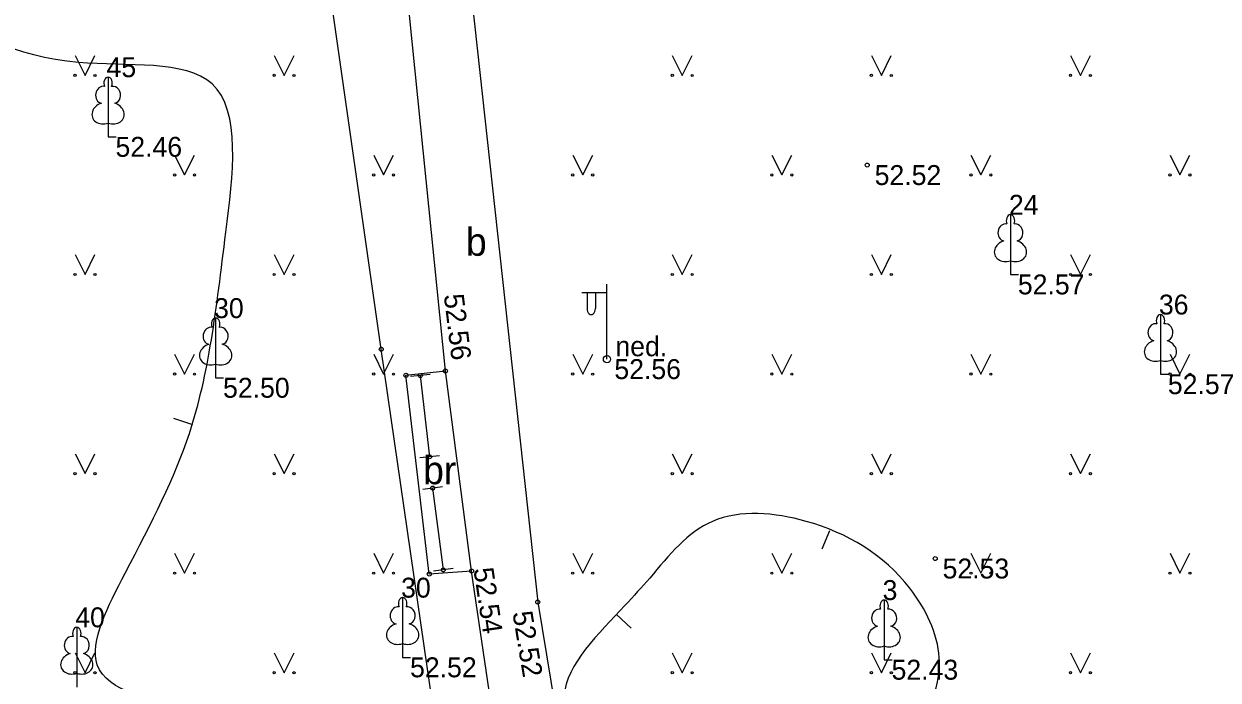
# Model space of a CAD drawing. Extents: x 619806 to 620082, y 405176 to 405386.
# Drawn here: x 619968.46 to 619998.46, y 405224.81 to 405241.29 of the extents above; entities that cross this region are included whole.
import ezdxf

# ---------------------------------------------------------------- set-up
doc = ezdxf.new("R2010")
doc.units = 0
for name, color, linetype in [('APGS_ELEM_####_####_#', 7, 'Continuous'), ('APGS_ELEM_####_TKST_#', 7, 'Continuous'), ('APGS_VADP_ZSPR_####_#', 7, 'Continuous'), ('BUVE_SOLS_####_####_#', 7, 'Continuous'), ('CELI_CMAL_####_####_#', 7, 'Continuous'), ('CELI_CSEG_####_TKST_#', 7, 'Continuous'), ('CELI_SEGL_####_####_#', 7, 'Continuous'), ('RELJ_AATZ_####_TKST_#', 7, 'Continuous'), ('RELJ_ELEM_####_####_#', 7, 'Continuous'), ('RELJ_HORZ_PAMT_####_#', 7, 'Continuous'), ('TERT_DIAM_####_TKST_#', 7, 'Continuous'), ('TERT_ELEM_####_####_#', 7, 'Continuous')]:
    doc.layers.add(name, color=color, linetype=linetype)

msp = doc.modelspace()

# ---------------------------------------------------------------- linework, layer by layer
at = {"layer": 'APGS_ELEM_####_####_#'}
for p, q in [((619983.109, 405234.542), (619982.474, 405234.537)), ((619982.609, 405234.538), (619982.609, 405234.146)), ((619982.819, 405234.54), (619982.819, 405234.146)), ((619983.109, 405232.875), (619983.109, 405234.758))]:
    msp.add_line(p, q, dxfattribs=at)
msp.add_circle((619983.109, 405232.875), 0.09, dxfattribs=at)
msp.add_ellipse((619982.714, 405234.146), major_axis=(0, 0.151), ratio=0.695971, start_param=1.570796, end_param=4.712389, dxfattribs=at)
at = {"layer": 'APGS_VADP_ZSPR_####_#'}
msp.add_lwpolyline([(619938.618, 405223.547), (619972.929, 405204.127), (619985.155, 405202.826), (619985.811, 405203.238), (619985.154, 405203.005), (619983.308, 405203.577), (619978.291, 405211.172), (619979.175, 405220.104), (619979.035, 405222.014), (619979.51, 405222.264), (619979.008, 405222.268), (619977.44, 405233.124), (619976.223, 405241.622), (619977.344, 405241.94), (619976.176, 405241.874), (619974.789, 405253.607), (619974.705, 405261.349), (619975.127, 405262.48)], dxfattribs=at)
at = {"layer": 'BUVE_SOLS_####_####_#'}
for p, q in [((619978.668, 405232.492), (619978.172, 405232.436)), ((619978.902, 405230.45), (619978.406, 405230.394)), ((619978.979, 405229.669), (619978.483, 405229.605)), ((619978.731, 405229.637), (619978.997, 405227.583)), ((619979.245, 405227.615), (619978.749, 405227.551))]:
    msp.add_line(p, q, dxfattribs=at)
msp.add_lwpolyline([(619978.42, 405232.464), (619978.654, 405230.422)], dxfattribs=at)
at = {"layer": 'CELI_CMAL_####_####_#'}
for points in [[(619982.283, 405204.018), (619982.381, 405205.526), (619981.404, 405213.543), (619980.879, 405217.395), (619980.193, 405224.262), (619979.707, 405227.554), (619978.646, 405227.479), (619978.06, 405232.469), (619979.052, 405232.579), (619978.008, 405242.924), (619976.591, 405255.672), (619975.781, 405263.512), (619969.844, 405259.482), (619963.066, 405254.752), (619955.624, 405249.587), (619947.422, 405243.791), (619942.081, 405239.98), (619941.835, 405240.299), (619936.133, 405229.455), (619943.441, 405225.387), (619954.092, 405219.528), (619965.106, 405213.442), (619974.994, 405207.99), (619982.283, 405204.018)], [(619978.832, 405249.941), (619981.369, 405226.774), (619981.804, 405224.124), (619982.441, 405217.773), (619982.996, 405213.675), (619983.965, 405205.418), (619983.685, 405203.225), (619985.778, 405202.103), (619986.248, 405201.889), (619987.106, 405201.651), (619987.96, 405201.56), (619988.713, 405201.545), (619992.1, 405202.316), (619994.967, 405203.071), (620002.119, 405213.03), (620010.184, 405224.469), (620017.253, 405234.372), (620024.304, 405244.304)]]:
    msp.add_lwpolyline(points, dxfattribs=at)
at = {"layer": 'CELI_SEGL_####_####_#'}
msp.add_lwpolyline([(619979.707, 405227.554), (619979.052, 405232.579)], dxfattribs=at)
at = {"layer": 'RELJ_ELEM_####_####_#'}
for centre in [(619989.646, 405237.748), (619977.44, 405233.124), (619978.06, 405232.469), (619978.42, 405232.464), (619979.052, 405232.579), (619978.654, 405230.422), (619978.731, 405229.637), (619991.352, 405227.867), (619978.997, 405227.583), (619979.707, 405227.554), (619978.646, 405227.479), (619981.369, 405226.774)]:
    msp.add_circle(centre, 0.05, dxfattribs=at)
at = {"layer": 'RELJ_HORZ_PAMT_####_#'}
for p, q in [((619972.222, 405231.391), (619972.697, 405231.236)), ((619988.513, 405228.108), (619988.709, 405228.568)), ((619983.72, 405226.123), (619983.351, 405226.459))]:
    msp.add_line(p, q, dxfattribs=at)
for points in [[(619952.192, 405242.46), (619958.269, 405245.178), (619960.212, 405247.147), (619962.71, 405245.388), (619969.834, 405240.326), (619973.191, 405239.787), (619973.537, 405236.062), (619972.621, 405231.011), (619971.007, 405227.497), (619970.308, 405225.195), (619972.877, 405224.18), (619975.834, 405223.443), (619975.125, 405220.25), (619977.669, 405218.792), (619978.775, 405216.928), (619978.459, 405213.841), (619976.501, 405213.003), (619972.992, 405212.359), (619969.535, 405213.328), (619966.616, 405215.931), (619967.251, 405218.057), (619966.078, 405220.067), (619963.269, 405223.678), (619959.906, 405226.02), (619956.916, 405226.372), (619951.315, 405227.272), (619948.301, 405227.78), (619946.134, 405229.326), (619943.292, 405232.49), (619942.821, 405234.331), (619944.296, 405235.783), (619946.209, 405238.021), (619948.046, 405239.888), (619950.691, 405241.967), (619952.192, 405242.46)], [(619984.185, 405227.378), (619985.762, 405228.802), (619988.112, 405228.802), (619990.713, 405227.124), (619991.454, 405225.372), (619990.633, 405223.024), (619987.075, 405219.79), (619984.539, 405219.79), (619983.041, 405222.072), (619982.032, 405224.412), (619983.558, 405226.687), (619984.185, 405227.378)]]:
    msp.add_spline(points, degree=3, dxfattribs=at)
at = {"layer": 'TERT_ELEM_####_####_#'}
for p, q in [((619969.75, 405240.5), (619970, 405240)), ((619970, 405240), (619970.25, 405240.5)), ((619974.75, 405240.5), (619975, 405240)), ((619975, 405240), (619975.25, 405240.5)), ((619984.75, 405240.5), (619985, 405240)), ((619985, 405240), (619985.25, 405240.5)), ((619989.75, 405240.5), (619990, 405240)), ((619990, 405240), (619990.25, 405240.5)), ((619994.75, 405240.5), (619995, 405240)), ((619995, 405240), (619995.25, 405240.5)), ((619970.58, 405238.804), (619970.58, 405238.457)), ((619970.58, 405238.457), (619970.78, 405238.457)), ((619972.25, 405238), (619972.5, 405237.5)), ((619972.5, 405237.5), (619972.75, 405238)), ((619977.25, 405238), (619977.5, 405237.5)), ((619977.5, 405237.5), (619977.75, 405238)), ((619982.25, 405238), (619982.5, 405237.5)), ((619982.5, 405237.5), (619982.75, 405238)), ((619987.25, 405238), (619987.5, 405237.5)), ((619987.5, 405237.5), (619987.75, 405238)), ((619992.25, 405238), (619992.5, 405237.5)), ((619992.5, 405237.5), (619992.75, 405238)), ((619997.25, 405238), (619997.5, 405237.5)), ((619997.5, 405237.5), (619997.75, 405238)), ((619969.75, 405235.5), (619970, 405235)), ((619970, 405235), (619970.25, 405235.5)), ((619974.75, 405235.5), (619975, 405235)), ((619975, 405235), (619975.25, 405235.5)), ((619984.75, 405235.5), (619985, 405235)), ((619985, 405235), (619985.25, 405235.5)), ((619989.75, 405235.5), (619990, 405235)), ((619990, 405235), (619990.25, 405235.5)), ((619994.75, 405235.5), (619995, 405235)), ((619995, 405235), (619995.25, 405235.5)), ((619993.243, 405235.348), (619993.243, 405235.001)), ((619993.243, 405235.001), (619993.443, 405235.001)), ((619972.25, 405233), (619972.5, 405232.5)), ((619972.5, 405232.5), (619972.75, 405233)), ((619977.25, 405233), (619977.5, 405232.5)), ((619977.5, 405232.5), (619977.75, 405233)), ((619982.25, 405233), (619982.5, 405232.5)), ((619982.5, 405232.5), (619982.75, 405233)), ((619987.25, 405233), (619987.5, 405232.5)), ((619987.5, 405232.5), (619987.75, 405233)), ((619992.25, 405233), (619992.5, 405232.5)), ((619992.5, 405232.5), (619992.75, 405233)), ((619997.25, 405233), (619997.5, 405232.5)), ((619997.5, 405232.5), (619997.75, 405233)), ((619973.281, 405232.753), (619973.281, 405232.406)), ((619997.01, 405232.843), (619997.01, 405232.496)), ((619973.281, 405232.406), (619973.481, 405232.406)), ((619997.01, 405232.496), (619997.21, 405232.496)), ((619969.75, 405230.5), (619970, 405230)), ((619970, 405230), (619970.25, 405230.5)), ((619974.75, 405230.5), (619975, 405230)), ((619975, 405230), (619975.25, 405230.5)), ((619984.75, 405230.5), (619985, 405230)), ((619985, 405230), (619985.25, 405230.5)), ((619989.75, 405230.5), (619990, 405230)), ((619990, 405230), (619990.25, 405230.5)), ((619994.75, 405230.5), (619995, 405230)), ((619995, 405230), (619995.25, 405230.5)), ((619972.25, 405228), (619972.5, 405227.5)), ((619972.5, 405227.5), (619972.75, 405228)), ((619977.25, 405228), (619977.5, 405227.5)), ((619977.5, 405227.5), (619977.75, 405228)), ((619982.25, 405228), (619982.5, 405227.5)), ((619982.5, 405227.5), (619982.75, 405228)), ((619987.25, 405228), (619987.5, 405227.5)), ((619987.5, 405227.5), (619987.75, 405228)), ((619992.25, 405228), (619992.5, 405227.5)), ((619992.5, 405227.5), (619992.75, 405228)), ((619997.25, 405228), (619997.5, 405227.5)), ((619997.5, 405227.5), (619997.75, 405228)), ((619969.75, 405225.5), (619970, 405225)), ((619970, 405225), (619970.25, 405225.5)), ((619974.75, 405225.5), (619975, 405225)), ((619975, 405225), (619975.25, 405225.5)), ((619977.978, 405225.733), (619977.978, 405225.386)), ((619984.75, 405225.5), (619985, 405225)), ((619985, 405225), (619985.25, 405225.5)), ((619989.75, 405225.5), (619990, 405225)), ((619990, 405225), (619990.25, 405225.5)), ((619990.071, 405225.673), (619990.071, 405225.326)), ((619994.75, 405225.5), (619995, 405225)), ((619995, 405225), (619995.25, 405225.5)), ((619977.978, 405225.386), (619978.178, 405225.386)), ((619990.071, 405225.326), (619990.271, 405225.326)), ((619969.794, 405224.988), (619969.794, 405224.641))]:
    msp.add_line(p, q, dxfattribs=at)
for points in [[(619970.58, 405239.957), (619970.58, 405238.804)], [(619970.67, 405239.725), (619970.669, 405239.726)], [(619993.243, 405236.501), (619993.243, 405235.348)], [(619993.333, 405236.269), (619993.332, 405236.27)], [(619973.281, 405233.906), (619973.281, 405232.753)], [(619997.01, 405233.996), (619997.01, 405232.843)], [(619973.371, 405233.674), (619973.37, 405233.675)], [(619997.1, 405233.764), (619997.099, 405233.765)], [(619977.978, 405226.886), (619977.978, 405225.733)], [(619990.071, 405226.826), (619990.071, 405225.673)], [(619978.068, 405226.654), (619978.067, 405226.655)], [(619990.161, 405226.594), (619990.16, 405226.595)], [(619969.794, 405226.141), (619969.794, 405224.988)], [(619969.884, 405225.909), (619969.883, 405225.91)]]:
    msp.add_lwpolyline(points, dxfattribs=at)
for centre, radius in [((619969.75, 405240), 0.028), ((619970.25, 405240), 0.0263), ((619974.75, 405240), 0.028), ((619975.25, 405240), 0.0263), ((619984.75, 405240), 0.028), ((619985.25, 405240), 0.0263), ((619989.75, 405240), 0.028), ((619990.25, 405240), 0.0263), ((619994.75, 405240), 0.028), ((619995.25, 405240), 0.0263), ((619972.25, 405237.5), 0.028), ((619972.75, 405237.5), 0.0263), ((619977.25, 405237.5), 0.028), ((619977.75, 405237.5), 0.0263), ((619982.25, 405237.5), 0.028), ((619982.75, 405237.5), 0.0263), ((619987.25, 405237.5), 0.028), ((619987.75, 405237.5), 0.0263), ((619992.25, 405237.5), 0.028), ((619992.75, 405237.5), 0.0263), ((619997.25, 405237.5), 0.028), ((619997.75, 405237.5), 0.0263), ((619969.75, 405235), 0.028), ((619970.25, 405235), 0.0263), ((619974.75, 405235), 0.028), ((619975.25, 405235), 0.0263), ((619984.75, 405235), 0.028), ((619985.25, 405235), 0.0263), ((619989.75, 405235), 0.028), ((619990.25, 405235), 0.0263), ((619994.75, 405235), 0.028), ((619995.25, 405235), 0.0263), ((619972.25, 405232.5), 0.028), ((619972.75, 405232.5), 0.0263), ((619977.25, 405232.5), 0.028), ((619977.75, 405232.5), 0.0263), ((619982.25, 405232.5), 0.028), ((619982.75, 405232.5), 0.0263), ((619987.25, 405232.5), 0.028), ((619987.75, 405232.5), 0.0263), ((619992.25, 405232.5), 0.028), ((619992.75, 405232.5), 0.0263), ((619997.25, 405232.5), 0.028), ((619997.75, 405232.5), 0.0263), ((619969.75, 405230), 0.028), ((619970.25, 405230), 0.0263), ((619974.75, 405230), 0.028), ((619975.25, 405230), 0.0263), ((619984.75, 405230), 0.028), ((619985.25, 405230), 0.0263), ((619989.75, 405230), 0.028), ((619990.25, 405230), 0.0263), ((619994.75, 405230), 0.028), ((619995.25, 405230), 0.0263), ((619972.25, 405227.5), 0.028), ((619972.75, 405227.5), 0.0263), ((619977.25, 405227.5), 0.028), ((619977.75, 405227.5), 0.0263), ((619982.25, 405227.5), 0.028), ((619982.75, 405227.5), 0.0263), ((619987.25, 405227.5), 0.028), ((619987.75, 405227.5), 0.0263), ((619992.25, 405227.5), 0.028), ((619992.75, 405227.5), 0.0263), ((619997.25, 405227.5), 0.028), ((619997.75, 405227.5), 0.0263), ((619969.75, 405225), 0.028), ((619970.25, 405225), 0.0263), ((619974.75, 405225), 0.028), ((619975.25, 405225), 0.0263), ((619984.75, 405225), 0.028), ((619985.25, 405225), 0.0263), ((619989.75, 405225), 0.028), ((619990.25, 405225), 0.0263), ((619994.75, 405225), 0.028), ((619995.25, 405225), 0.0263)]:
    msp.add_circle(centre, radius, dxfattribs=at)
for centre, major_axis, ratio, start_param, end_param in [((619970.58, 405239.807), (0, -0.15), 0.707107, 3.14537, 5.287485), ((619970.58, 405239.807), (0, -0.15), 0.707107, 0.995701, 3.137816), ((619970.452, 405239.512), (-0.039, -0.212), 0.861323, 3.141593, 6.283185), ((619970.708, 405239.512), (0.039, -0.212), 0.861323, 0, 3.141593), ((619970.49, 405239.05), (0.307, 0.095), 0.814445, 1.570796, 4.752015), ((619970.67, 405239.05), (-0.307, 0.095), 0.814445, 1.531171, 4.712389), ((619993.115, 405236.056), (-0.039, -0.212), 0.861323, 3.141593, 6.283185), ((619993.243, 405236.351), (0, -0.15), 0.707107, 3.14537, 5.287485), ((619993.243, 405236.351), (0, -0.15), 0.707107, 0.995701, 3.137816), ((619993.371, 405236.056), (0.039, -0.212), 0.861323, 0, 3.141593), ((619993.153, 405235.594), (0.307, 0.095), 0.814445, 1.570796, 4.752015), ((619993.333, 405235.594), (-0.307, 0.095), 0.814445, 1.531171, 4.712389), ((619973.281, 405233.756), (0, -0.15), 0.707107, 3.14537, 5.287485), ((619973.281, 405233.756), (0, -0.15), 0.707107, 0.995701, 3.137816), ((619997.01, 405233.846), (0, -0.15), 0.707107, 3.14537, 5.287485), ((619997.01, 405233.846), (0, -0.15), 0.707107, 0.995701, 3.137816), ((619973.153, 405233.461), (-0.039, -0.212), 0.861323, 3.141593, 6.283185), ((619973.409, 405233.461), (0.039, -0.212), 0.861323, 0, 3.141593), ((619996.882, 405233.551), (-0.039, -0.212), 0.861323, 3.141593, 6.283185), ((619997.138, 405233.551), (0.039, -0.212), 0.861323, 0, 3.141593), ((619996.92, 405233.089), (0.307, 0.095), 0.814445, 1.570796, 4.752015), ((619997.1, 405233.089), (-0.307, 0.095), 0.814445, 1.531171, 4.712389), ((619973.191, 405232.999), (0.307, 0.095), 0.814445, 1.570796, 4.752015), ((619973.371, 405232.999), (-0.307, 0.095), 0.814445, 1.531171, 4.712389), ((619977.978, 405226.736), (0, -0.15), 0.707107, 3.14537, 5.287485), ((619977.978, 405226.736), (0, -0.15), 0.707107, 0.995701, 3.137816), ((619990.071, 405226.676), (0, -0.15), 0.707107, 3.14537, 5.287485), ((619990.071, 405226.676), (0, -0.15), 0.707107, 0.995701, 3.137816), ((619977.85, 405226.441), (-0.039, -0.212), 0.861323, 3.141593, 6.283185), ((619978.106, 405226.441), (0.039, -0.212), 0.861323, 0, 3.141593), ((619989.943, 405226.381), (-0.039, -0.212), 0.861323, 3.141593, 6.283185), ((619990.199, 405226.381), (0.039, -0.212), 0.861323, 0, 3.141593), ((619969.794, 405225.991), (0, -0.15), 0.707107, 3.14537, 5.287485), ((619969.794, 405225.991), (0, -0.15), 0.707107, 0.995701, 3.137816), ((619977.888, 405225.979), (0.307, 0.095), 0.814445, 1.570796, 4.752015), ((619978.068, 405225.979), (-0.307, 0.095), 0.814445, 1.531171, 4.712389), ((619989.981, 405225.919), (0.307, 0.095), 0.814445, 1.570796, 4.752015), ((619990.161, 405225.919), (-0.307, 0.095), 0.814445, 1.531171, 4.712389), ((619969.666, 405225.696), (-0.039, -0.212), 0.861323, 3.141593, 6.283185), ((619969.922, 405225.696), (0.039, -0.212), 0.861323, 0, 3.141593), ((619969.704, 405225.234), (0.307, 0.095), 0.814445, 1.570796, 4.752015), ((619969.884, 405225.234), (-0.307, 0.095), 0.814445, 1.531171, 4.712389)]:
    msp.add_ellipse(centre, major_axis=major_axis, ratio=ratio, start_param=start_param, end_param=end_param, dxfattribs=at)

# ---------------------------------------------------------------- texts
at = {"layer": 'APGS_ELEM_####_TKST_#'}
msp.add_text('ned.', height=0.5, dxfattribs=at).set_placement((619983.321, 405232.948))
at = {"layer": 'CELI_CSEG_####_TKST_#'}
for s, p in [('b', (619979.567, 405235.471)), ('br', (619978.492, 405229.735))]:
    msp.add_text(s, height=0.7, dxfattribs=at).set_placement(p)
at = {"layer": 'RELJ_AATZ_####_TKST_#'}
for s, p in [(' 52.46', (619970.58, 405237.957)), (' 52.52', (619989.646, 405237.248)), (' 52.57', (619993.243, 405234.501)), (' 52.56', (619983.109, 405232.375)), (' 52.50', (619973.281, 405231.906)), (' 52.57', (619997.01, 405231.996)), (' 52.53', (619991.352, 405227.367)), (' 52.52', (619977.978, 405224.886)), (' 52.43', (619990.071, 405224.826))]:
    msp.add_text(s, height=0.5, dxfattribs=at).set_placement(p)
for s, rotation, p in [(' 52.56', 276.8358, (619978.988, 405234.671)), (' 52.54', 278.398, (619979.728, 405227.791)), (' 52.52', 279.322, (619980.704, 405226.693))]:
    msp.add_text(s, height=0.5, rotation=rotation, dxfattribs=at).set_placement(p)
at = {"layer": 'TERT_DIAM_####_TKST_#'}
for s, p in [(' 45', (619970.355, 405239.957)), (' 24', (619993.018, 405236.501)), (' 36', (619996.785, 405233.996)), (' 30', (619973.056, 405233.906)), (' 30', (619977.753, 405226.886)), (' 3', (619989.846, 405226.826)), (' 40', (619969.569, 405226.141))]:
    msp.add_text(s, height=0.5, dxfattribs=at).set_placement(p)

doc.saveas('drawing.dxf')
